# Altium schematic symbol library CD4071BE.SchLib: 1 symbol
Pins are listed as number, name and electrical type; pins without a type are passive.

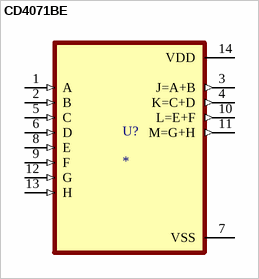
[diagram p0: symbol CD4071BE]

## CD4071BE
designator U?
4-ch 2-input 3-V to 18-V OR gate; MF: Texas Instruments; MP: CD4071BE
footprint DIP794W45P254L1969H508Q14
pins: 1 A (in), 2 B (in), 3 J=A+B (out), 4 K=C+D (out), 5 C (in), 6 D (in), 7 VSS (power), 8 E (in), 9 F (in), 10 L=E+F (out), 11 M=G+H (out), 12 G (in), 13 H (in), 14 VDD (power)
